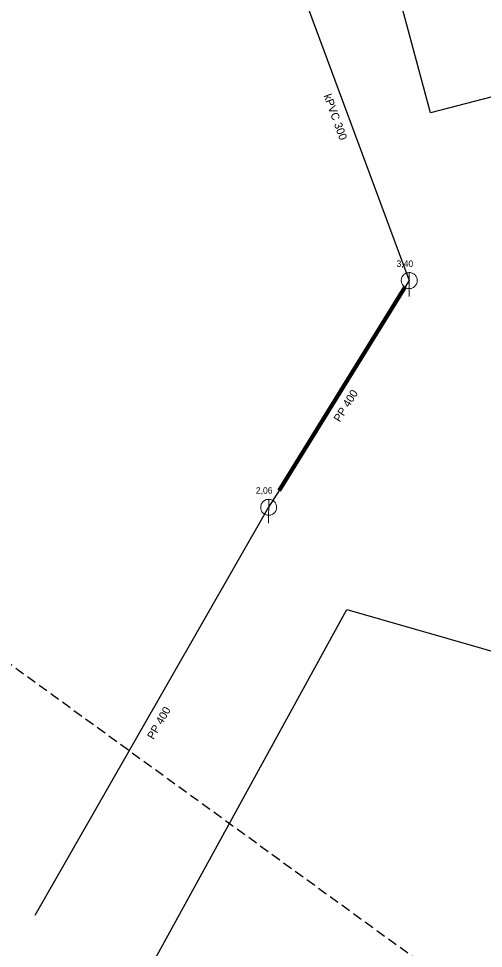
# Model space of a CAD drawing. Extents: x -683466 to -682479, y -996772 to -995963.
# Drawn here: x -682775.1 to -682717, y -996583.8 to -996467.6 of the extents above; entities that cross this region are included whole.
import ezdxf

# ---------------------------------------------------------------- set-up
doc = ezdxf.new("R2010")
doc.units = 0
doc.header["$LTSCALE"] = 0.4
doc.linetypes.add('MEDIUM_DASHED', pattern=[4.5, 3, -1.5])
doc.layers.add('1', color=7, linetype='Continuous')
for name, color, linetype, lineweight in [('14', 7, 'Continuous', 25), ('17', 7, 'Continuous', 25), ('2', 7, 'Continuous', 106), ('22', 7, 'Continuous', 13), ('63', 7, 'MEDIUM_DASHED', 25)]:
    doc.layers.add(name, color=color, linetype=linetype, lineweight=lineweight)

msp = doc.modelspace()

# ---------------------------------------------------------------- linework, layer by layer
at = {"layer": '14'}
for p, q in [((-682741.09, -996460.359), (-682726.26, -996500.32)), ((-682743.85, -996528.66), (-682773.109, -996579.67))]:
    msp.add_line(p, q, dxfattribs=at)
msp.add_lwpolyline([(-682726.26, -996500.32), (-682726.789, -996501.1), (-682742.55, -996526.559), (-682743.85, -996528.66)], dxfattribs=at)
at = {"layer": '17'}
for points in [[(-682688.579, -996470.29), (-682723.62, -996479.34), (-682739.951, -996418.663), (-682751.718, -996421.207)], [(-682853.964, -996772.18), (-682857.831, -996766.21), (-682841.943, -996716.943), (-682820.103, -996698.697), (-682782.754, -996630.021), (-682734.074, -996541.419), (-682713.035, -996547.471), (-682692.053, -996520.101)]]:
    msp.add_lwpolyline(points, dxfattribs=at)
at = {"layer": '2'}
msp.add_line((-682726.789, -996501.1), (-682742.55, -996526.559), dxfattribs=at)
at = {"layer": '2', "lineweight": 100}
msp.add_line((-682726.789, -996501.1), (-682742.55, -996526.559), dxfattribs=at)
at = {"layer": '22'}
for p, q in [((-682726.26, -996502.32), (-682726.259, -996499.32)), ((-682743.85, -996530.66), (-682743.849, -996527.66))]:
    msp.add_line(p, q, dxfattribs=at)
for points in [[(-682725.26, -996500.32), (-682725.265, -996500.211), (-682725.283, -996500.103), (-682725.313, -996499.997), (-682725.353, -996499.896), (-682725.405, -996499.799), (-682725.467, -996499.709), (-682725.539, -996499.626), (-682725.619, -996499.552), (-682725.707, -996499.486), (-682725.801, -996499.431), (-682725.901, -996499.386), (-682726.006, -996499.353), (-682726.113, -996499.331), (-682726.222, -996499.321), (-682726.332, -996499.323), (-682726.44, -996499.337), (-682726.547, -996499.362), (-682726.65, -996499.399), (-682726.748, -996499.448), (-682726.84, -996499.506), (-682726.926, -996499.575), (-682727.003, -996499.652), (-682727.072, -996499.738), (-682727.131, -996499.83), (-682727.179, -996499.928), (-682727.216, -996500.031), (-682727.242, -996500.138), (-682727.256, -996500.246), (-682727.259, -996500.356), (-682727.249, -996500.465), (-682727.228, -996500.572), (-682727.194, -996500.676), (-682727.15, -996500.776), (-682727.095, -996500.871), (-682727.029, -996500.959), (-682726.955, -996501.039), (-682726.872, -996501.111), (-682726.782, -996501.173), (-682726.686, -996501.225), (-682726.584, -996501.266), (-682726.479, -996501.296), (-682726.371, -996501.314), (-682726.261, -996501.32), (-682726.152, -996501.314), (-682726.044, -996501.296), (-682725.939, -996501.267), (-682725.837, -996501.226), (-682725.74, -996501.174), (-682725.65, -996501.112), (-682725.567, -996501.041), (-682725.492, -996500.961), (-682725.427, -996500.873), (-682725.371, -996500.779), (-682725.327, -996500.679), (-682725.293, -996500.575), (-682725.271, -996500.467), (-682725.261, -996500.358)], [(-682742.85, -996528.66), (-682742.855, -996528.551), (-682742.873, -996528.443), (-682742.903, -996528.337), (-682742.943, -996528.236), (-682742.995, -996528.139), (-682743.057, -996528.049), (-682743.129, -996527.966), (-682743.209, -996527.892), (-682743.297, -996527.826), (-682743.391, -996527.771), (-682743.491, -996527.726), (-682743.596, -996527.693), (-682743.703, -996527.671), (-682743.812, -996527.661), (-682743.922, -996527.663), (-682744.03, -996527.677), (-682744.137, -996527.702), (-682744.24, -996527.739), (-682744.338, -996527.788), (-682744.43, -996527.846), (-682744.516, -996527.915), (-682744.593, -996527.992), (-682744.662, -996528.078), (-682744.721, -996528.17), (-682744.769, -996528.268), (-682744.806, -996528.371), (-682744.832, -996528.478), (-682744.846, -996528.586), (-682744.849, -996528.696), (-682744.839, -996528.805), (-682744.818, -996528.912), (-682744.784, -996529.016), (-682744.74, -996529.116), (-682744.685, -996529.211), (-682744.619, -996529.299), (-682744.545, -996529.379), (-682744.462, -996529.451), (-682744.372, -996529.513), (-682744.276, -996529.565), (-682744.174, -996529.606), (-682744.069, -996529.636), (-682743.961, -996529.654), (-682743.851, -996529.66), (-682743.742, -996529.654), (-682743.634, -996529.636), (-682743.529, -996529.607), (-682743.427, -996529.566), (-682743.33, -996529.514), (-682743.24, -996529.452), (-682743.157, -996529.381), (-682743.082, -996529.301), (-682743.017, -996529.213), (-682742.961, -996529.119), (-682742.917, -996529.019), (-682742.883, -996528.915), (-682742.861, -996528.807), (-682742.851, -996528.698)]]:
    msp.add_lwpolyline(points, close=True, dxfattribs=at)
at = {"layer": '63'}
msp.add_lwpolyline([(-683425.281, -996021.839), (-683425.281, -996016.256), (-683425.281, -996016.256), (-683335.962, -995963.223), (-683335.962, -995963.223), (-682479.059, -996630.324), (-682479.059, -996630.324), (-682551.631, -996711.269), (-682551.631, -996711.269), (-683416.907, -996083.246), (-683416.907, -996083.246)], close=True, dxfattribs=at)

# ---------------------------------------------------------------- texts
at = {"layer": '1'}
for s, rotation, p in [('kPVC 300', 290, (-682736.99, -996477.212)), ('PP 400', 58, (-682734.949, -996518.085)), ('PP 400', 60, (-682758.249, -996557.755))]:
    msp.add_text(s, height=1, rotation=rotation, dxfattribs=at).set_placement(p)
for s, p in [('3,40', (-682727.86, -996498.608)), ('2,06', (-682745.449, -996526.948))]:
    msp.add_text(s, height=0.8, dxfattribs=at).set_placement(p)

doc.saveas('drawing.dxf')
